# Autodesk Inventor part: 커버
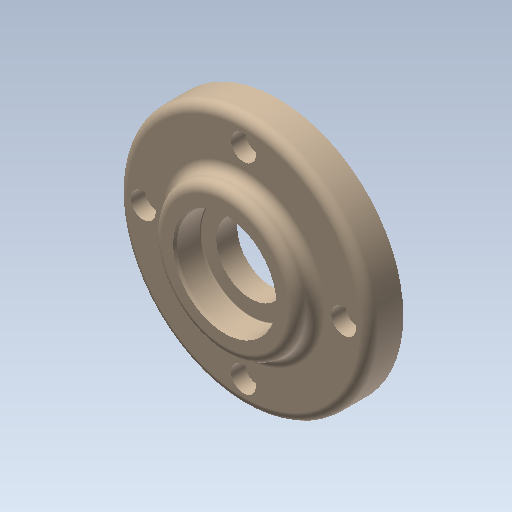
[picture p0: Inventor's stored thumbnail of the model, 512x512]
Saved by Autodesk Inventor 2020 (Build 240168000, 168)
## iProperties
Created: 2011-02
Part Number: 커버
Document SubType Name: Modeling
Designer: pww
Density: 1 g/cm^3
Material: 알루미늄 6061
Appearance: 기본값(2)
Author: pww
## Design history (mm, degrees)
sketch "스케치1"
  geometry: C1 r 40 at (0, 0) reference
extrude "돌출1" new body sketch "스케치1" distance "d2" = 11; taper "d3" = 0 deg
sketch "스케치2"
  geometry: C1 r 23 at (0, 0); 1 further point
  constraints: 1 centre point, 1 coincident
  dimensions: "d4" = 46 diameter of C1
extrude "돌출2" join sketch "스케치2" distance "d5" = 6; taper "d6" = 0 deg
sketch "스케치3"
  geometry: C1 r 23.5 at (0, 0); 1 further point
  constraints: 1 centre point, 1 coincident
  dimensions: "d7" = 47 diameter of C1
extrude "돌출3" join sketch "스케치3" distance "d8" = 3; taper "d9" = 0 deg
hole "구멍1" diameter "d12" = 22; stored, may be unused: countersink angle "d16" = 90 deg, drill point angle "d18" = 118 deg; dims "d13" = 6, "d14" = 32, "d15" = 8.3, "d17" = 8, "d49" = 10, "d50" = 10
hole "구멍2" diameter "d21" = 40; stored, may be unused: countersink angle "d25" = 90 deg, drill point angle "d27" = 0 deg; dims "d22" = 6, "d23" = 32, "d24" = 8, "d26" = 5, "d44" = 10, "d45" = 10
fillet "모깎기1" dims "d28" = 3, "d43" = 0.3
chamfer "모따기1" distance "d29" = 0.8; stored, may be unused: second distance "d30" = 2, angle "d31" = 30 deg
sketch "스케치4"
  geometry: C1 r 1.621 at (0, -32) reference; 2 further points
  constraints: 1 coincident, 1 vertical alignment
hole "구멍3" sketch "스케치4" at (0, -32) diameter "d33" = 4.5; stored, may be unused: countersink angle "d37" = 90 deg, drill point angle "d39" = 118 deg; dims "d34" = 6, "d35" = 8, "d36" = 4.6, "d38" = 5
chamfer "모따기2" distance "d46" = 1; stored, may be unused: second distance "d47" = 2, angle "d48" = 45 deg
node "솔리드1"
pattern_circular "원형 패턴1" dims angle "d41" = 360 deg
node "참조1"
node "참조2"
